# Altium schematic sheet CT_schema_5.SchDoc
size 368 x 336 mm
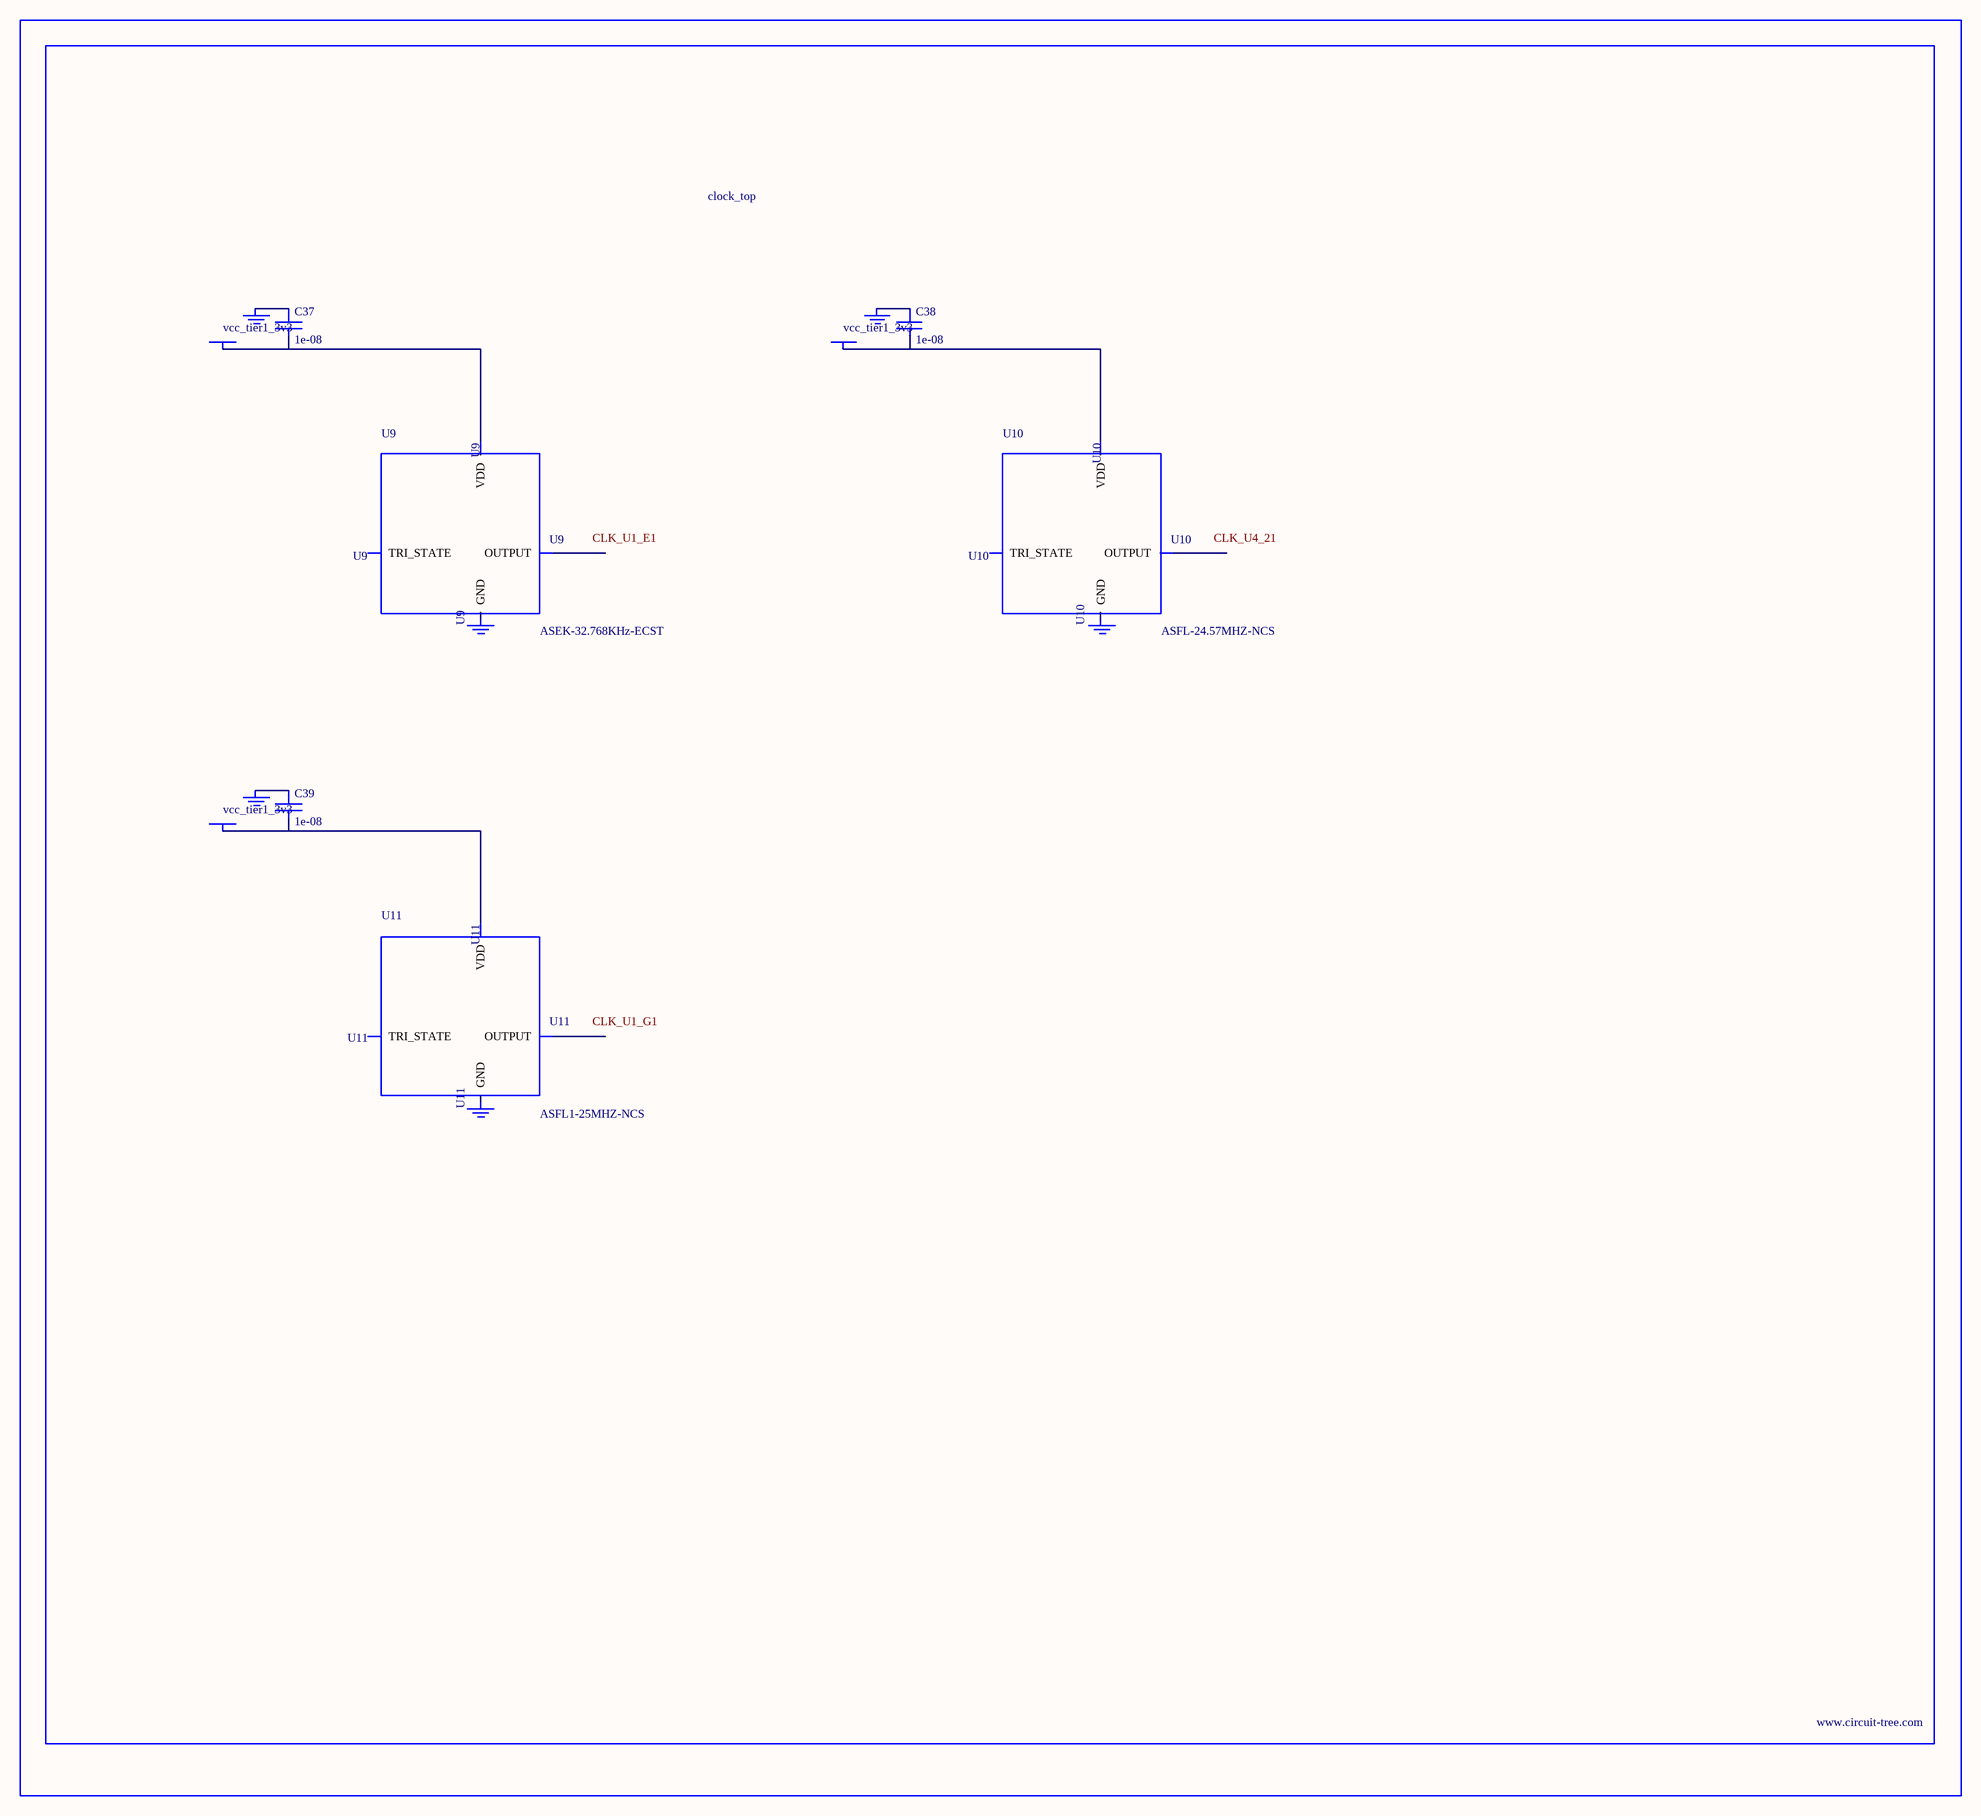
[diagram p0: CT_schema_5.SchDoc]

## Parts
BORDER4  (no value)
C37  1e-08  [C0402]
C38  1e-08  [C0402]
C39  1e-08  [C0402]
GND_INSTANCE_4_0  (no value)
GND_INSTANCE_4_1  (no value)
GND_INSTANCE_4_2  (no value)
GND_INSTANCE_4_3  (no value)
GND_INSTANCE_4_4  (no value)
GND_INSTANCE_4_5  (no value)
POWER_INSTANCE_4_0  vcc_tier1_3v3
POWER_INSTANCE_4_1  vcc_tier1_3v3
POWER_INSTANCE_4_2  vcc_tier1_3v3
U9  ASEK-32.768KHz-ECST  [ASEK]
U10  ASFL-24.57MHZ-NCS  [ASFL1]
U11  ASFL1-25MHZ-NCS  [ASFL1]

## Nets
NetC37_1: C37.1 GND_INSTANCE_4_0.0(GND)
NetC37_2: C37.2 POWER_INSTANCE_4_0.0(PWR) U9.4(VDD)
NetC38_1: C38.1 GND_INSTANCE_4_2.0(GND)
NetC38_2: C38.2 POWER_INSTANCE_4_1.0(PWR) U10.4(VDD)
NetC39_1: C39.1 GND_INSTANCE_4_4.0(GND)
NetC39_2: C39.2 POWER_INSTANCE_4_2.0(PWR) U11.4(VDD)

Not connected (* = marked no-connect by the designer): GND_INSTANCE_4_1 0(GND); GND_INSTANCE_4_3 0(GND); GND_INSTANCE_4_5 0(GND); U9 1(TRI_STATE) 2(GND) 3(OUTPUT); U10 1(TRI_STATE) 2(GND) 3(OUTPUT); U11 1(TRI_STATE) 2(GND) 3(OUTPUT)

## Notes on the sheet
- Labels drawn without touching a wire or pin: CLK_U1_E1, CLK_U1_G1, CLK_U4_21

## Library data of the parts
BORDER4 = BORDER_PAGE4
C37-C39 = C0402C103K3RAC
GND_INSTANCE_4_0-GND_INSTANCE_4_5 = GND
POWER_INSTANCE_4_0-POWER_INSTANCE_4_2 = PWR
